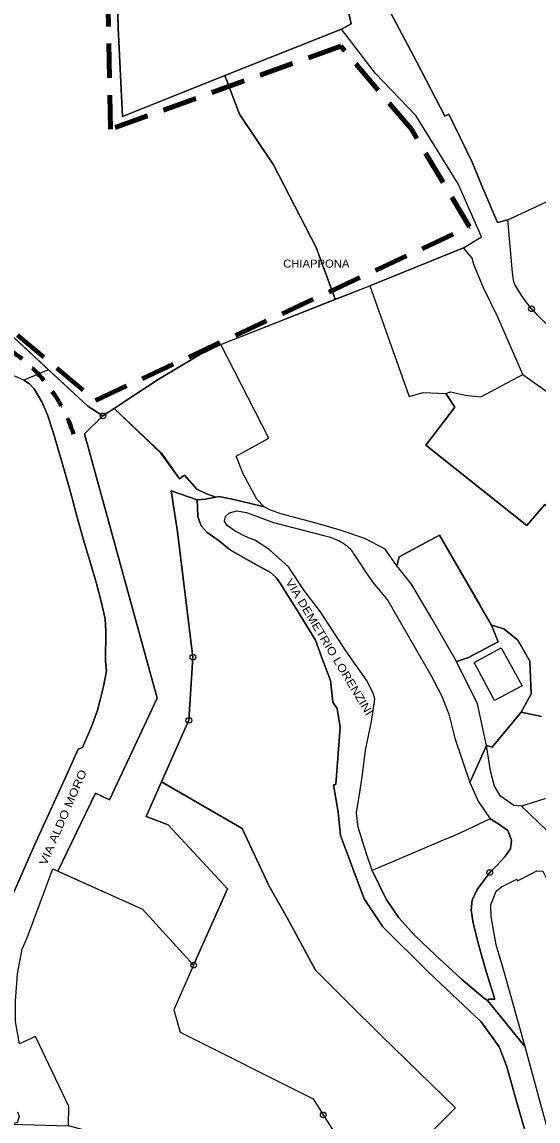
# Model space of a CAD drawing. Extents: x 654952 to 658955, y 890426 to 894481.
# Drawn here: x 657629.2 to 657809.7, y 891531.5 to 891916.2 of the extents above; entities that cross this region are included whole.
import ezdxf

# ---------------------------------------------------------------- set-up
doc = ezdxf.new("R2010")
doc.units = 0
doc.header["$LTSCALE"] = 4
doc.header["$PDMODE"] = 32
doc.header["$PDSIZE"] = 2
doc.linetypes.add('MEDIUM_DASHED', pattern=[4.5, 3, -1.5])
doc.linetypes.add('SHORT_DASHED', pattern=[2.7, 1.5, -1.2])
for name, color, linetype, lineweight in [('1', 7, 'Continuous', 25), ('11', 7, 'Continuous', 25), ('12', 7, 'Continuous', 25), ('14', 7, 'Continuous', 25), ('16', 7, 'Continuous', 25), ('19', 7, 'Continuous', 25), ('26', 7, 'Continuous', 25), ('32', 7, 'Continuous', 25), ('41', 7, 'SHORT_DASHED', 80), ('5', 7, 'Continuous', 25), ('55', 7, 'Continuous', 25), ('7', 7, 'MEDIUM_DASHED', 100), ('9', 7, 'Continuous', 25)]:
    doc.layers.add(name, color=color, linetype=linetype, lineweight=lineweight)
doc.layers.add('58', color=7, linetype='Continuous')

msp = doc.modelspace()

# ---------------------------------------------------------------- linework, layer by layer
at = {"layer": '1'}
for points in [[(657781.15, 891692.39), (657785.39, 891693.77), (657795.73, 891699.31), (657793.41, 891705.09), (657797.68, 891703.87), (657802.67, 891699.81), (657806.86, 891692.47), (657807.28, 891681.11), (657803.78, 891674.63), (657793.67, 891662.43), (657791.66, 891662.93), (657788.51, 891677.6)], [(657787.38, 891692.06), (657796.82, 891697.12), (657804.2, 891683.9), (657794.48, 891678.76)]]:
    msp.add_lwpolyline(points, close=True, dxfattribs=at)
at = {"layer": '11'}
for points in [[(657698.71, 891803.37), (657691.3, 891799.75), (657676.78, 891791.06), (657661.49, 891780.98)], [(657690.3, 891752.72), (657693.75, 891751.11), (657695.7, 891750.35), (657696.98, 891749.94), (657698, 891750.1), (657702.72, 891749.17), (657708.2, 891747.88), (657713.96, 891746.51), (657711.31, 891749.26), (657706.6, 891758.1), (657704.12, 891764.22), (657715.51, 891770.6), (657698.71, 891803.37)], [(657661.49, 891780.98), (657677.96, 891765.33), (657684.3, 891756.36), (657686.05, 891757.67), (657690.3, 891752.72)]]:
    msp.add_lwpolyline(points, dxfattribs=at)
at = {"layer": '12'}
msp.add_line((657700.14, 891897.46), (657740.93, 891913.75), dxfattribs=at)
for points in [[(657662.1, 891944.72), (657662.89, 891914.18), (657664.35, 891883.16), (657680.65, 891889.73), (657700.14, 891897.46)], [(657740.93, 891913.75), (657744.38, 891915.57), (657743.11, 891920.79), (657742.96, 891925.58)]]:
    msp.add_lwpolyline(points, dxfattribs=at)
msp.add_lwpolyline([(657664.35, 891883.16), (657700.14, 891897.46), (657680.65, 891889.73)], close=True, dxfattribs=at)
at = {"layer": '14'}
for p, q in [((657688.99, 891693.92), (657683.58, 891737.74)), ((657687.55, 891671.8), (657688.99, 891693.92)), ((657671.35, 891605.74), (657689.24, 891586.11))]:
    msp.add_line(p, q, dxfattribs=at)
for points in [[(657810.96, 891673.1), (657803.78, 891674.63), (657807.28, 891681.11), (657806.86, 891692.47), (657802.67, 891699.81), (657797.68, 891703.87), (657793.41, 891705.09), (657775.28, 891736.56), (657761.08, 891728.99), (657760.25, 891725.89), (657756.18, 891731.74), (657749.15, 891735.49), (657740.54, 891738.4), (657731.57, 891740.9), (657719.7, 891744.05), (657715.85, 891745.46), (657713.96, 891746.51), (657711.31, 891749.26), (657706.6, 891758.1), (657704.12, 891764.22), (657715.51, 891770.6), (657698.71, 891803.37), (657750.86, 891823.91), (657764.66, 891785.1), (657769.46, 891786.57), (657777.47, 891786.24), (657780.57, 891781.45), (657770.43, 891768.16), (657805.8, 891739.98), (657812.04, 891747.32)], [(657657.52, 891778.36), (657651.05, 891772.05), (657676.43, 891679.61)], [(657683.58, 891737.74), (657681.36, 891752.17), (657690.47, 891748.99), (657693.41, 891749.17), (657696.98, 891749.94), (657695.7, 891750.35), (657693.75, 891751.11), (657690.3, 891752.72), (657686.05, 891757.67), (657684.3, 891756.36), (657677.74, 891765.36), (657661.49, 891780.98), (657657.52, 891778.36)], [(657676.43, 891679.61), (657659.86, 891643.99), (657654.9, 891646.35), (657641.68, 891619.02), (657671.35, 891605.74)], [(657689.24, 891586.11), (657701.05, 891612.8), (657680.36, 891635.17), (657672.68, 891638.11), (657677.99, 891650.3), (657687.55, 891671.8)]]:
    msp.add_lwpolyline(points, dxfattribs=at)
for p in [(657657.52, 891778.36), (657688.99, 891693.92), (657687.55, 891671.8)]:
    msp.add_point(p, dxfattribs=at)
at = {"layer": '16'}
for points in [[(657805.8, 891739.98), (657770.43, 891768.16), (657780.57, 891781.45), (657777.47, 891786.24), (657779.09, 891786.74), (657784.33, 891785.6), (657789.7, 891785.05), (657804.34, 891792.9), (657839.27, 891768.03)], [(657839.27, 891768.03), (657828.94, 891752.66), (657821.03, 891740.63), (657812.04, 891747.32), (657805.8, 891739.98)]]:
    msp.add_lwpolyline(points, dxfattribs=at)
at = {"layer": '19'}
msp.add_line((657730.99, 891539.3), (657734.55, 891533.67), dxfattribs=at)
for points in [[(657616.23, 891815.12), (657638.47, 891794.53), (657629.79, 891790.88), (657626.92, 891792.11)], [(657707.63, 891736.08), (657703.75, 891738), (657701.01, 891740.02), (657700.01, 891741.53), (657700.34, 891743.09), (657701.76, 891744.45), (657704.35, 891745.09), (657707.7, 891744.51)], [(657707.7, 891744.51), (657717.14, 891741.02), (657734.82, 891736.52)], [(657747.47, 891647.36), (657748.29, 891652.8), (657749.39, 891661.39), (657751.45, 891671.34), (657752.59, 891679.2), (657752.01, 891681.26), (657749.72, 891685.84), (657742.48, 891696.11), (657733.56, 891709.81), (657727.95, 891717.21), (657722.41, 891725.52), (657715.64, 891731.6), (657710.64, 891734.82), (657707.63, 891736.08)], [(657745.58, 891729.48), (657749.83, 891723.1), (657752.14, 891719.79), (657757.1, 891713.69), (657772.22, 891687.58), (657776.02, 891680.31), (657778.45, 891673.94), (657780.58, 891665.58), (657785.82, 891650), (657788.78, 891643.49), (657792.9, 891637.35), (657780.34, 891631.39), (657777.13, 891630.04), (657751.62, 891619.27)], [(657677.99, 891650.3), (657672.68, 891638.11), (657680.36, 891635.17), (657701.05, 891612.8), (657689.24, 891586.11)], [(657677.99, 891650.3), (657672.68, 891638.11), (657680.36, 891635.17)], [(657780.86, 891536.17), (657754.8, 891561.49), (657743.68, 891572.55), (657731.8, 891584.3), (657721.93, 891602.67), (657715.62, 891613.72), (657706.24, 891633.92), (657677.99, 891650.3)], [(657751.62, 891619.27), (657749.63, 891625.47), (657746.81, 891634.42), (657746.24, 891639.41), (657747.47, 891647.36)], [(657680.36, 891635.17), (657701.05, 891612.8), (657689.24, 891586.11), (657682.3, 891570.49), (657684.55, 891562.67), (657730.99, 891539.3)], [(657734.55, 891533.67), (657744.04, 891518.8), (657738.12, 891505.34), (657727.6, 891493.76), (657732.33, 891489.03), (657771.18, 891491.81), (657759.86, 891514.99), (657780.86, 891536.17)]]:
    msp.add_lwpolyline(points, dxfattribs=at)
msp.add_spline([(657734.82, 891736.52), (657738.55, 891735.34), (657743.82, 891731.89), (657745.58, 891729.48)], degree=3, dxfattribs=at)
msp.add_point((657734.55, 891533.67), dxfattribs=at)
at = {"layer": '26'}
for points in [[(657742.74, 891969.03), (657743.62, 891962.05), (657744.69, 891956.96), (657745.87, 891951.55), (657746.96, 891946.43), (657748.9, 891940.97), (657750.54, 891935.67), (657752.22, 891931.58), (657755.25, 891924.94), (657761.15, 891913.87), (657767.14, 891902.38), (657777.05, 891883.31), (657778.51, 891883.96), (657786.61, 891867.17), (657790.42, 891858.02), (657795.5, 891846.02)], [(657795.5, 891846.02), (657799.15, 891847.04), (657827.65, 891860.23), (657883.09, 891886.04), (657903.22, 891849.7), (657908.58, 891840.1), (657991.89, 891886.8)]]:
    msp.add_lwpolyline(points, dxfattribs=at)
at = {"layer": '32'}
for p, q in [((657740.93, 891913.75), (657700.14, 891897.46)), ((657738.79, 891819.16), (657750.86, 891823.91))]:
    msp.add_line(p, q, dxfattribs=at)
for points in [[(657680.65, 891889.73), (657680.65, 891889.73), (657664.35, 891883.16), (657662.89, 891914.18), (657662.06, 891946.06), (657661.2, 891962.02), (657657.2, 891961.01)], [(657330.48, 891924.75), (657333.71, 891897.41), (657331.73, 891853.22), (657356.3, 891845.74), (657368.76, 891841.68), (657402.61, 891825.37), (657414.53, 891826.87), (657412.33, 891831.41), (657414.11, 891838.17), (657417.22, 891841.66), (657423.3, 891843.85), (657429.9, 891842.26), (657466.92, 891870.18), (657493.97, 891786.85), (657506.91, 891790.22), (657616.23, 891815.12), (657652.23, 891781.79)], [(657750.86, 891823.91), (657783.57, 891837.24), (657789.97, 891841.06), (657781.79, 891859.57), (657767.01, 891883.53), (657752.85, 891898.15), (657740.93, 891913.74)], [(657738.79, 891819.16), (657732.05, 891837.27), (657717.21, 891866.25), (657705.26, 891883.93), (657700.14, 891897.46), (657680.65, 891889.73)], [(657700.14, 891897.46), (657705.26, 891883.93), (657717.21, 891866.25), (657732.05, 891837.27), (657738.79, 891819.16)], [(657805.93, 891817.77), (657804.45, 891819.7), (657803.03, 891822.02), (657801.6, 891824.34), (657801.28, 891825.29), (657801.03, 891826.92), (657800.78, 891828.54), (657800.78, 891828.54), (657799.96, 891837.79), (657799.15, 891847.04), (657827.65, 891860.23), (657883.09, 891886.04), (657908.58, 891840.1)], [(657652.23, 891781.79), (657657.52, 891778.36), (657676.78, 891791.06), (657691.3, 891799.75), (657698.71, 891803.37), (657738.79, 891819.16)], [(657849.7, 891779.79), (657830.81, 891795.48), (657811.93, 891811.18), (657809.67, 891813.51), (657807.41, 891815.85), (657805.93, 891817.77)]]:
    msp.add_lwpolyline(points, dxfattribs=at)
at = {"layer": '41'}
msp.add_arc((657593.96, 891754.86), 55.94, 17.7593, 57.1028, dxfattribs=at)
at = {"layer": '5'}
for points in [[(657654.9, 891646.35), (657659.86, 891643.99), (657676.43, 891679.61), (657651.05, 891772.05), (657657.52, 891778.36), (657652.23, 891781.79), (657638.47, 891794.53), (657629.79, 891790.88)], [(657629.79, 891790.88), (657631.83, 891789.56), (657633.5, 891787.83), (657636.17, 891783.28), (657638.07, 891778.7)], [(657638.07, 891778.7), (657640.06, 891772.63), (657642.89, 891763.14), (657644.85, 891756.21), (657646.76, 891749.53), (657648.41, 891743.25), (657650.66, 891734.97), (657653.14, 891726.84), (657655.29, 891719.71), (657657, 891712.9), (657658.27, 891707.35), (657658.53, 891703.04), (657658.46, 891692.53)], [(657696.98, 891749.94), (657693.41, 891749.17), (657690.47, 891748.99)], [(657690.47, 891748.99), (657690.62, 891746.37), (657690.72, 891743.18), (657691.91, 891739.82), (657694, 891737.5), (657697.87, 891734.87), (657702.13, 891731.4), (657711.02, 891726.29), (657716.1, 891723.57), (657718.12, 891721.74), (657719.68, 891719.46), (657721.56, 891716.47), (657725.18, 891710.76), (657731.88, 891699.89), (657734, 891694.05), (657737.16, 891685.74), (657737.91, 891678.12), (657739.42, 891675.93), (657740.54, 891669.42)], [(657760.25, 891725.89), (657756.18, 891731.74), (657749.15, 891735.49), (657740.54, 891738.4), (657731.57, 891740.9), (657719.7, 891744.05), (657715.85, 891745.46), (657713.96, 891746.51), (657708.2, 891747.88), (657702.72, 891749.17), (657698, 891750.1), (657696.98, 891749.94)], [(657707.63, 891736.08), (657703.75, 891738), (657701.01, 891740.02), (657700.01, 891741.53), (657700.34, 891743.09), (657701.76, 891744.45), (657704.35, 891745.09), (657707.7, 891744.51)], [(657707.7, 891744.51), (657717.14, 891741.02), (657734.82, 891736.52)], [(657747.47, 891647.36), (657748.29, 891652.8), (657749.39, 891661.39), (657751.45, 891671.34), (657752.59, 891679.2), (657752.01, 891681.26), (657749.72, 891685.84), (657742.48, 891696.11), (657733.56, 891709.81), (657727.95, 891717.21), (657722.41, 891725.52), (657715.64, 891731.6), (657710.64, 891734.82), (657707.63, 891736.08)], [(657745.58, 891729.48), (657749.83, 891723.1), (657752.14, 891719.79), (657757.1, 891713.69), (657772.22, 891687.58), (657776.02, 891680.31), (657778.45, 891673.94), (657780.58, 891665.58)], [(657791.66, 891662.93), (657788.51, 891677.6), (657781.15, 891692.39), (657772.65, 891707.26), (657765.48, 891719.46), (657760.25, 891725.89)], [(657658.46, 891692.53), (657658.79, 891689.12), (657657.69, 891683.67), (657656.58, 891678.97), (657655.66, 891675.31), (657653.6, 891669.86), (657650.32, 891662.32), (657648.79, 891661.73), (657644.82, 891652.84), (657634.79, 891630.7), (657632.64, 891625.95), (657623.23, 891604.4), (657619.09, 891592)], [(657740.54, 891669.42), (657738.97, 891649.39), (657738.16, 891649.22), (657739.76, 891639.71), (657740.63, 891631.52)], [(657780.58, 891665.58), (657785.82, 891650), (657791.66, 891662.93)], [(657751.62, 891619.27), (657749.63, 891625.47), (657746.81, 891634.42), (657746.24, 891639.41), (657747.47, 891647.36)], [(657627.6, 891534.79), (657628.17, 891533.07), (657627.52, 891531), (657625.45, 891530.42), (657645.47, 891529.84), (657645.56, 891536.63), (657633.9, 891561.11), (657628.36, 891558.61), (657626.93, 891566.36), (657626.93, 891573.49), (657627.68, 891583.11), (657629.3, 891591.67), (657631.12, 891596.05), (657640, 891619.78), (657641.69, 891619.02), (657654.9, 891646.35)], [(657740.63, 891631.52), (657748.88, 891609.28), (657755.43, 891599.47), (657771.26, 891583.81), (657789.79, 891566.28), (657796.12, 891557.5), (657798.18, 891552.16), (657798.92, 891550.19)], [(657792.14, 891573.58), (657790.36, 891574.95), (657782.91, 891581.24), (657773.72, 891589.69), (657766.77, 891596.39), (657760.96, 891602.67), (657756.53, 891609.21), (657751.62, 891619.27)], [(657830.83, 891467.72), (657829.01, 891473.58), (657823.72, 891491.98), (657818.84, 891508.15), (657814.86, 891522.18), (657811.39, 891534.78), (657805.15, 891557.48), (657792.14, 891573.58)], [(657798.92, 891550.19), (657801.57, 891540.46), (657805.28, 891527.54), (657807.3, 891520.91), (657811.96, 891503.42), (657819.94, 891476.27), (657820.8, 891472.78), (657823.22, 891463.27), (657827.48, 891457.04), (657833.46, 891458.9), (657830.83, 891467.72)]]:
    msp.add_lwpolyline(points, dxfattribs=at)
msp.add_spline([(657734.82, 891736.52), (657738.55, 891735.34), (657743.82, 891731.89), (657745.58, 891729.48)], degree=3, dxfattribs=at)
at = {"layer": '55'}
for points in [[(657737.33, 891949.76), (657737.71, 891944.48), (657738.45, 891939.43), (657739.24, 891936.31), (657741.82, 891928.98), (657742.96, 891925.58), (657743.11, 891920.79), (657744.38, 891915.57), (657740.93, 891913.75), (657700.14, 891897.46)], [(657767.14, 891902.38), (657761.15, 891913.87), (657755.25, 891924.94), (657752.22, 891931.58), (657750.54, 891935.67)], [(657799.96, 891837.79), (657799.15, 891847.04), (657795.5, 891846.02), (657790.42, 891858.02), (657786.61, 891867.17), (657778.51, 891883.96), (657777.05, 891883.31), (657767.14, 891902.38)], [(657700.14, 891897.46), (657705.26, 891883.93), (657717.21, 891866.25), (657732.05, 891837.27), (657738.79, 891819.16), (657750.86, 891823.91), (657764.66, 891785.1), (657769.46, 891786.57), (657777.47, 891786.24), (657780.57, 891781.45), (657770.43, 891768.16), (657805.8, 891739.98), (657812.04, 891747.32), (657821.03, 891740.63), (657850.06, 891702.07), (657875.51, 891683.22), (657894.62, 891668.46), (657918.52, 891646.58), (657923.57, 891639.6)], [(657801.03, 891826.92), (657800.78, 891828.54), (657799.96, 891837.79)], [(657807.41, 891815.85), (657804.45, 891819.7), (657801.6, 891824.34), (657801.28, 891825.29), (657801.03, 891826.92)], [(657830.81, 891795.48), (657811.93, 891811.18), (657807.41, 891815.85)]]:
    msp.add_lwpolyline(points, dxfattribs=at)
msp.add_point((657807.41, 891815.85), dxfattribs=at)
at = {"layer": '7'}
msp.add_lwpolyline([(657326.96, 891719.28), (657394.25, 891834.07), (657408.5, 891829.37), (657417.46, 891846.55), (657435.38, 891850.29), (657467.48, 891876.44), (657496.6, 891792.02), (657613.82, 891818.17), (657654.89, 891783.8), (657785.69, 891844.55), (657765.39, 891878.68), (657740.75, 891907.82), (657660.12, 891878.68), (657658.62, 891957.13)], dxfattribs=at)
at = {"layer": '9'}
for p, q in [((657688.99, 891693.92), (657687.55, 891671.8)), ((657803.95, 891641.7), (657821.32, 891624.99)), ((657792.14, 891573.58), (657805.15, 891557.48))]:
    msp.add_line(p, q, dxfattribs=at)
for points in [[(657786.67, 891833.56), (657783.57, 891837.24), (657750.86, 891823.91)], [(657750.86, 891823.91), (657764.66, 891785.1), (657769.46, 891786.57), (657777.47, 891786.24), (657779.09, 891786.74), (657784.33, 891785.6), (657789.7, 891785.05), (657804.34, 891792.9), (657795.68, 891812.92), (657790.64, 891823.21), (657787.28, 891831.39), (657786.67, 891833.56)], [(657638.07, 891778.7), (657636.17, 891783.28), (657633.5, 891787.83), (657631.83, 891789.56), (657629.79, 891790.88), (657626.92, 891792.11), (657623.58, 891792.92), (657615.9, 891793.62), (657606.21, 891793.58), (657596.64, 891793.76), (657586.36, 891793.28), (657578.11, 891787.06)], [(657658.53, 891703.04), (657658.27, 891707.35), (657657, 891712.9), (657655.29, 891719.71), (657653.14, 891726.84), (657650.66, 891734.97), (657648.41, 891743.25), (657646.76, 891749.53), (657644.85, 891756.21), (657642.89, 891763.14), (657640.06, 891772.63), (657638.07, 891778.7)], [(657737.16, 891685.74), (657734, 891694.05), (657731.88, 891699.89), (657725.18, 891710.76), (657721.56, 891716.47), (657719.68, 891719.46), (657718.12, 891721.74), (657716.1, 891723.57), (657711.02, 891726.29), (657702.13, 891731.4), (657697.87, 891734.87), (657694, 891737.5), (657691.91, 891739.82), (657690.72, 891743.18), (657690.62, 891746.37), (657690.47, 891748.99), (657681.36, 891752.17), (657683.58, 891737.74), (657688.99, 891693.92)], [(657648.79, 891661.73), (657650.32, 891662.32), (657653.6, 891669.86), (657655.66, 891675.31), (657656.58, 891678.97), (657657.69, 891683.67), (657658.79, 891689.12), (657658.46, 891692.53), (657658.53, 891703.04)], [(657739.76, 891639.71), (657738.16, 891649.22), (657738.97, 891649.39), (657740.54, 891669.42), (657739.42, 891675.93), (657737.91, 891678.12), (657737.16, 891685.74)], [(657857.9, 891672.72), (657859.56, 891669.77), (657862.94, 891664.95), (657869.45, 891659.61), (657872.75, 891656.14), (657877.31, 891649.49), (657879.23, 891637.01), (657875.57, 891637.83), (657850.6, 891645.19), (657842.92, 891647.51), (657837.63, 891648.61), (657827.79, 891648.61), (657820.85, 891647.24), (657814.31, 891645.06), (657803.95, 891641.7), (657801.28, 891641.96), (657801.28, 891641.96), (657796.59, 891645.21), (657794.43, 891648.78), (657793.09, 891654.17), (657791.66, 891662.93), (657793.67, 891662.43), (657803.78, 891674.63), (657810.96, 891673.1)], [(657687.55, 891671.8), (657677.99, 891650.3), (657706.24, 891633.92), (657715.62, 891613.72)], [(657803.95, 891641.7), (657801.28, 891641.96), (657801.28, 891641.96), (657796.59, 891645.21), (657794.43, 891648.78), (657793.09, 891654.17), (657791.66, 891662.93), (657785.82, 891650)], [(657623.23, 891604.4), (657632.64, 891625.95), (657634.79, 891630.7), (657644.82, 891652.84), (657648.79, 891661.73)], [(657785.82, 891650), (657788.78, 891643.49), (657792.9, 891637.35)], [(657879.23, 891637.01), (657875.57, 891637.83), (657850.6, 891645.19), (657842.92, 891647.51), (657837.63, 891648.61), (657827.79, 891648.61), (657820.85, 891647.24), (657814.31, 891645.06), (657803.95, 891641.7)], [(657798.18, 891552.16), (657796.12, 891557.5), (657789.79, 891566.28), (657771.26, 891583.81), (657755.43, 891599.47), (657748.88, 891609.28), (657740.63, 891631.52), (657739.76, 891639.71)], [(657799.08, 891633.27), (657795.62, 891635.66), (657792.9, 891637.35), (657780.34, 891631.39), (657777.13, 891630.04), (657751.62, 891619.27)], [(657792.9, 891637.35), (657795.62, 891635.66), (657799.08, 891633.27), (657800.39, 891629.84)], [(657792.82, 891618.51), (657795.39, 891621.1), (657797.93, 891623.94), (657800.01, 891626.78), (657800.39, 891629.84), (657799.08, 891633.27)], [(657800.39, 891629.84), (657800.01, 891626.78), (657797.93, 891623.94), (657795.39, 891621.1), (657792.82, 891618.51)], [(657626.93, 891573.49), (657627.68, 891583.11), (657629.3, 891591.67), (657631.12, 891596.05), (657640, 891619.78), (657671.35, 891605.74), (657689.24, 891586.11)], [(657751.62, 891619.27), (657756.53, 891609.21), (657760.96, 891602.67), (657766.77, 891596.39), (657773.72, 891589.69), (657782.91, 891581.24), (657790.36, 891574.95), (657792.14, 891573.58), (657792.36, 891574.14)], [(657792.82, 891618.51), (657788.36, 891612.54), (657786.62, 891608.86), (657786.34, 891605.48), (657787.04, 891600.83), (657788.98, 891593.02), (657791.58, 891583.85), (657794.57, 891574.25), (657792.36, 891574.14), (657792.14, 891573.58), (657805.15, 891557.48)], [(657792.36, 891574.14), (657794.57, 891574.25), (657791.58, 891583.85), (657788.98, 891593.02), (657787.04, 891600.83), (657786.34, 891605.48), (657786.62, 891608.86), (657788.36, 891612.54), (657792.82, 891618.51)], [(657805.15, 891557.48), (657797.89, 891583.73), (657795.1, 891593.25), (657793.26, 891603.11), (657793.15, 891607.22), (657795.07, 891612.02), (657796.86, 891613.55), (657802.31, 891616.15), (657802.56, 891615.64), (657807.54, 891618.24), (657809.29, 891619.09), (657811.32, 891619), (657812.36, 891617.17), (657820.46, 891599.62), (657823.4, 891592.46), (657830.88, 891573.05), (657832.38, 891568.94), (657848.72, 891526.75), (657850.81, 891522.18), (657851.67, 891519.51), (657852.88, 891517.99)], [(657814.86, 891522.18), (657811.39, 891534.78), (657805.15, 891557.48), (657797.89, 891583.73), (657795.1, 891593.25), (657793.26, 891603.11), (657793.15, 891607.22), (657795.07, 891612.02), (657796.86, 891613.55), (657802.31, 891616.15), (657802.56, 891615.64), (657807.54, 891618.24), (657809.29, 891619.09), (657811.32, 891619), (657812.36, 891617.17), (657820.46, 891599.62), (657823.4, 891592.46), (657830.88, 891573.05), (657832.38, 891568.94), (657848.72, 891526.75)], [(657715.62, 891613.72), (657721.93, 891602.67), (657731.8, 891584.3), (657743.68, 891572.55), (657754.8, 891561.49), (657780.86, 891536.17), (657759.86, 891514.99), (657771.18, 891491.81), (657732.33, 891489.03), (657754.48, 891465.47), (657757.95, 891460.5), (657758.94, 891453.37), (657757.14, 891448.91), (657755.13, 891446.87)], [(657689.24, 891586.11), (657682.3, 891570.49), (657684.55, 891562.67), (657730.99, 891539.3), (657734.55, 891533.67), (657744.04, 891518.8), (657738.12, 891505.34), (657727.6, 891493.76), (657723.06, 891499.45), (657675.43, 891520.8), (657666.96, 891524.08), (657645.47, 891529.84), (657645.56, 891536.63), (657633.9, 891561.11), (657628.36, 891558.61), (657626.93, 891566.36), (657626.93, 891573.49)], [(657820.8, 891472.78), (657819.94, 891476.27), (657811.96, 891503.42), (657807.3, 891520.91), (657805.28, 891527.54), (657801.57, 891540.46), (657798.92, 891550.19), (657798.18, 891552.16)]]:
    msp.add_lwpolyline(points, dxfattribs=at)
msp.add_lwpolyline([(657760.25, 891725.89), (657761.08, 891728.99), (657775.28, 891736.56), (657789.35, 891712.23), (657793.41, 891705.09), (657795.73, 891699.31), (657785.39, 891693.77), (657781.15, 891692.39), (657772.65, 891707.26), (657765.48, 891719.46)], close=True, dxfattribs=at)
for p in [(657688.99, 891693.92), (657687.55, 891671.8), (657792.82, 891618.51), (657689.24, 891586.11)]:
    msp.add_point(p, dxfattribs=at)

# ---------------------------------------------------------------- texts
at = {"layer": '58', "width": 1.05}
msp.add_text('CHIAPPONA', height=2.801, dxfattribs=at).set_placement((657720.55, 891830.27))
at = {"layer": '58'}
for s, height, rotation, width, p in [('VIA DEMETRIO LORENZINI', 2.802, 301.142, 1.15, (657721.26, 891720.31)), ('VIA ALDO MORO', 2.799, 66.654, 1.2, (657637.7, 891620.77))]:
    msp.add_text(s, height=height, rotation=rotation, dxfattribs=dict(at, width=width)).set_placement(p)

doc.saveas('drawing.dxf')
